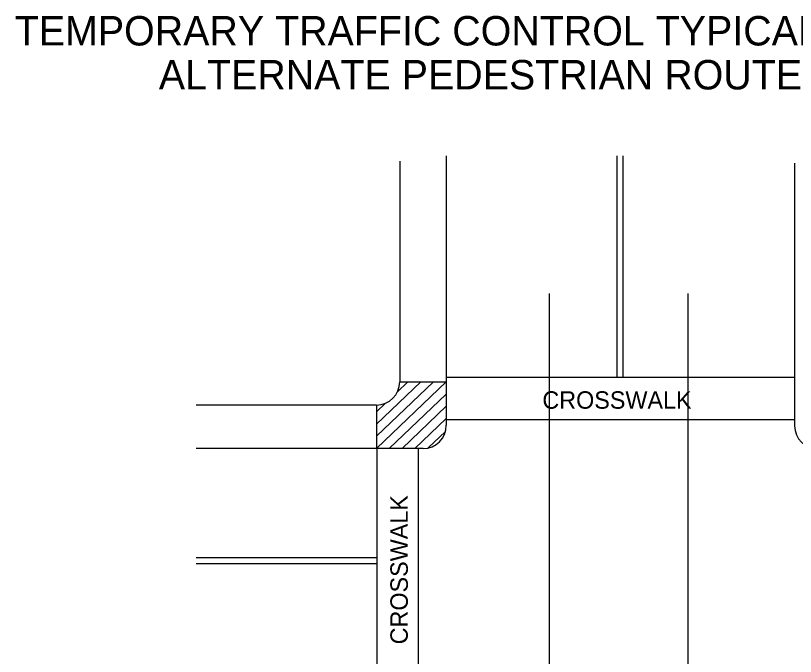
# Model space of a CAD drawing. Extents: x 12.69 to 19.62, y 5.94 to 15.87.
# Drawn here: x 12.694 to 15.342, y 13.692 to 15.869 of the extents above; entities that cross this region are included whole.
import ezdxf

# ---------------------------------------------------------------- set-up
doc = ezdxf.new("R2010")
doc.units = 0
for name, color, linetype in [('DETL-LINE', 7, 'Continuous'), ('ENGLISH', 7, 'Continuous'), ('V7_LEVEL_1', 7, 'Continuous')]:
    doc.layers.add(name, color=color, linetype=linetype)

msp = doc.modelspace()

# ---------------------------------------------------------------- linework, layer by layer
at = {"layer": 'DETL-LINE'}
for p, q in [((13.9197, 14.3983), (14.1569, 14.6249)), ((13.9197, 14.4812), (14.0701, 14.6249)), ((13.9197, 14.4398), (14.1135, 14.6249)), ((13.9911, 14.5909), (14.0266, 14.6249)), ((13.9987, 14.6249), (14.1569, 14.6249)), ((13.9631, 14.3983), (14.1569, 14.5834)), ((13.9197, 14.5227), (13.9503, 14.552)), ((13.9197, 14.5458), (13.9197, 14.3983)), ((14.0065, 14.3983), (14.1569, 14.5419)), ((14.05, 14.3983), (14.1569, 14.5004)), ((14.0955, 14.4003), (14.154, 14.4561))]:
    msp.add_line(p, q, dxfattribs=at)
at = {"layer": 'V7_LEVEL_1'}
for p, q in [((14.1569, 15.3928), (14.1569, 14.4773)), ((14.7362, 15.3928), (14.7362, 14.6392)), ((14.7568, 15.3928), (14.7568, 14.6392)), ((13.9987, 15.3747), (13.9987, 14.6249)), ((15.3398, 15.3674), (15.3398, 14.4739)), ((14.5059, 14.9247), (14.5059, 9.3607)), ((14.9772, 14.9247), (14.9772, 9.4166)), ((15.3398, 14.6392), (14.1569, 14.6392)), ((13.9197, 14.5459), (13.3076, 14.5459)), ((14.1569, 14.4974), (15.3398, 14.4974)), ((14.0779, 14.3983), (13.3076, 14.3983)), ((13.9206, 14.3983), (13.9206, 13.6362)), ((14.0624, 13.6362), (14.0624, 14.3983)), ((13.9206, 14.0274), (13.3076, 14.0274)), ((13.9206, 14.0068), (13.3076, 14.0068))]:
    msp.add_line(p, q, dxfattribs=at)
for centre, start, end in [((13.9197, 14.6249), 270, 0), ((14.0778, 14.4773), 270, 0), ((15.4189, 14.4756), 180, 270)]:
    msp.add_arc(centre, 0.0791, start, end, dxfattribs=at)

# ---------------------------------------------------------------- texts
at = {"layer": 'ENGLISH'}
for s, p in [('TEMPORARY TRAFFIC CONTROL TYPICAL APPLICATION FOR SIDEWALK CLOSURE', (12.6912, 15.7674)), ('ALTERNATE PEDESTRIAN ROUTE USING ROADWAY LANE OR SHOULDER', (13.1806, 15.6181))]:
    msp.add_text(s, height=0.1, dxfattribs=at).set_placement(p)
at = {"layer": 'V7_LEVEL_1'}
msp.add_text('CROSSWALK', height=0.0593, dxfattribs=at).set_placement((14.4831, 14.5335))
msp.add_text('CROSSWALK', height=0.0593, rotation=90, dxfattribs=at).set_placement((14.0262, 13.7333))

doc.saveas('drawing.dxf')
